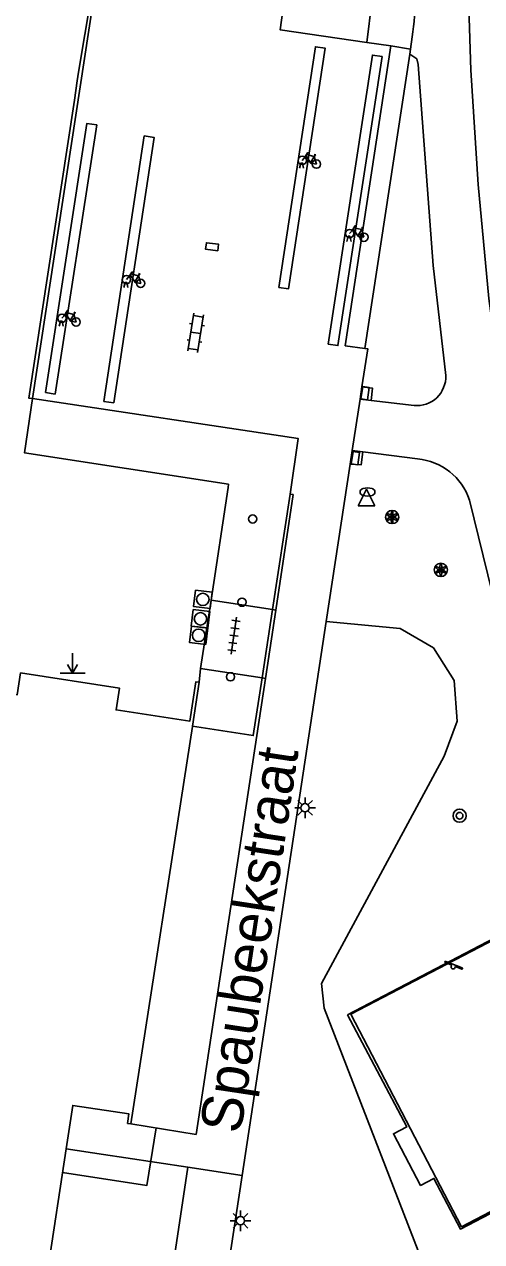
# Model space of a CAD drawing. Extents: x 125000 to 129004, y 397500 to 399008.
# Drawn here: x 126355.6 to 126383.3, y 398833.9 to 398907.4 of the extents above; entities that cross this region are included whole.
import ezdxf

# ---------------------------------------------------------------- set-up
doc = ezdxf.new("R2010")
doc.units = 0
for name, color, linetype in [('bs-afsc-poort', 7, 'Continuous'), ('gg-afsc-hekwerk', 7, 'Continuous'), ('gg-anno-openbare ruimte label', 7, 'Continuous'), ('gg-bbg-hoofdgebouw', 7, 'Continuous'), ('gg-knt-verharding', 7, 'Continuous'), ('gg-knt-verharding nz', 7, 'Continuous'), ('gt-grn-groengrens', 7, 'Continuous'), ('gt-grn-weggrens', 7, 'Continuous'), ('gt-symb-boom', 7, 'Continuous'), ('gt-symb-brandkraan', 7, 'Continuous'), ('gt-symb-fietsenrek', 7, 'Continuous'), ('gt-symb-klinker verharding', 7, 'Continuous'), ('gt-symb-kolk center center', 7, 'Continuous'), ('gt-symb-lichtmast', 7, 'Continuous'), ('gt-symb-markant object', 7, 'Continuous'), ('gt-symb-rioolschacht', 7, 'Continuous'), ('gt-symb-solitaire heester', 7, 'Continuous'), ('gt-symb-speelvoorziening', 7, 'Continuous'), ('gt-symb-tegel verharding', 7, 'Continuous'), ('gt-symb-vlaggenmast', 7, 'Continuous'), ('gt-symb-waterafsluiter', 7, 'Continuous')]:
    doc.layers.add(name, color=color, linetype=linetype)

# ---------------------------------------------------------------- blocks, each defined once
blk = doc.blocks.new('gt0-FREK')
at = {"layer": 'gt-symb-fietsenrek'}
for p, q in [((0.259, 0.762), (0.294, 0.823)), ((0.54, 0.335), (0.259, 0.762)), ((0.294, 0.823), (0.767, 0.714)), ((0.757, 0.841), (0.866, 0.816)), ((0.767, 0.714), (0.84, 0.822)), ((0.767, 0.714), (0.54, 0.335)), ((0.895, 0.252), (0.767, 0.714))]:
    blk.add_line(p, q, dxfattribs=at)
for points in [[(0.036, 0.476), (0.228, 0.708), (0.259, 0.762)], [(0.294, 0.823), (0.36, 0.937), (0.452, 0.935)], [(-0.124, 0), (-0.047, 0.312), (0.053, 0.312), (0.12, 0)], [(0.54, 0.335), (0.555, 0.305), (0.895, 0.252)]]:
    blk.add_lwpolyline(points, dxfattribs=at)
for centre in [(0.036, 0.476), (0.895, 0.252)]:
    blk.add_circle(centre, 0.252, dxfattribs=at)
blk = doc.blocks.new('gt0-KOLKCC')
at = {"layer": 'gt-symb-kolk center center'}
blk.add_lwpolyline([(-0.375, 0.2), (0.375, 0.2), (0.375, -0.2), (-0.375, -0.2)], close=True, dxfattribs=at)
blk = doc.blocks.new('gt0-BR')
at = {"layer": 'gt-symb-brandkraan'}
for centre, radius, start, end in [((-0.244, 0), 0.206, 107.56694, 252.43307), ((0.599, -2.664), 3, 106.89205, 107.56694), ((0, -0.691), 0.938, 73.10799, 106.89205), ((-0.599, -2.664), 3, 72.43309, 73.10799), ((0.244, 0), 0.206, 287.56695, 72.43309), ((0.599, 2.664), 3, 252.43307, 253.10797), ((0, 0.691), 0.938, 253.10797, 286.89206), ((-0.599, 2.664), 3, 286.89206, 287.56695)]:
    blk.add_arc(centre, radius, start, end, dxfattribs=at)
blk = doc.blocks.new('gt0-VMAST')
at = {"layer": 'gt-symb-vlaggenmast'}
blk.add_circle((0, 0), 0.25, dxfattribs=at)
blk = doc.blocks.new('gt0-KL1')
at = {"layer": 'gt-symb-klinker verharding'}
for p, q in [((-1.15, 0.3), (1.15, 0.3)), ((-1, -0.3), (-1, 0.3)), ((-0.5, 0.3), (-0.5, 0.45)), ((0, -0.3), (0, 0.3)), ((0.5, 0.3), (0.5, 0.45)), ((1, -0.3), (1, 0.3)), ((-1.15, -0.3), (1.15, -0.3)), ((-0.5, -0.45), (-0.5, -0.3)), ((0.5, -0.45), (0.5, -0.3))]:
    blk.add_line(p, q, dxfattribs=at)
blk = doc.blocks.new('gt0-MARKOB')
at = {"layer": 'gt-symb-markant object'}
for p, q in [((0, 0), (0, 1.2)), ((-0.75, 0), (0.75, 0)), ((0, 0), (-0.3, 0.52)), ((0, 0), (0.3, 0.52))]:
    blk.add_line(p, q, dxfattribs=at)
blk = doc.blocks.new('gt0-TEG1')
at = {"layer": 'gt-symb-tegel verharding'}
for p, q in [((-1.125, 0), (1.125, 0)), ((-0.9, -0.25), (-0.9, 0.25)), ((-0.45, -0.25), (-0.45, 0.25)), ((0, -0.25), (0, 0.25)), ((0.45, -0.25), (0.45, 0.25)), ((0.9, -0.25), (0.9, 0.25))]:
    blk.add_line(p, q, dxfattribs=at)
blk = doc.blocks.new('gt0-RS')
at = {"layer": 'gt-symb-rioolschacht'}
blk.add_lwpolyline([(-0.5, -0.5), (0.5, -0.5), (0.5, 0.5), (-0.5, 0.5)], close=True, dxfattribs=at)
blk.add_circle((0, 0), 0.375, dxfattribs=at)
blk = doc.blocks.new('gt0-LMAST')
at = {"layer": 'gt-symb-lichtmast'}
for p, q in [((-0.182, 0.173), (-0.447, 0.438)), ((-0.005, 0.246), (-0.005, 0.621)), ((0.172, 0.173), (0.437, 0.438)), ((-0.255, -0.004), (-0.63, -0.004)), ((-0.182, -0.181), (-0.447, -0.446)), ((-0.005, -0.254), (-0.005, -0.629)), ((0.437, -0.446), (0.172, -0.181)), ((0.245, -0.004), (0.62, -0.004))]:
    blk.add_line(p, q, dxfattribs=at)
blk.add_circle((-0.005, -0.004), 0.25, dxfattribs=at)
blk = doc.blocks.new('gt0-SV')
at = {"layer": 'gt-symb-speelvoorziening'}
for p, q in [((-0.477, 0.255), (-0.08, 0.096)), ((0.542, -0.076), (-0.449, 0.324)), ((0.125, 0.014), (0.515, -0.143))]:
    blk.add_line(p, q, dxfattribs=at)
for centre, radius, start, end in [((-0.466, 0.291), 0.0369, 63.6251, 252.66016), ((-0.002, -0.005), 0.128, 127.68665, 8.59861), ((0.531, -0.111), 0.0363, 243.50852, 72.54358)]:
    blk.add_arc(centre, radius, start, end, dxfattribs=at)
blk = doc.blocks.new('gt0-BOOM')
at = {"layer": 'gt-symb-boom'}
for radius in [0.4, 0.2]:
    blk.add_circle((0, 0), radius, dxfattribs=at)
blk = doc.blocks.new('gt0-SH')
at = {"layer": 'gt-symb-solitaire heester'}
blk.add_circle((0, 0), 0.4, dxfattribs=at)
for centre, start, end in [((-0.346, 0.2), 270, 30), ((-0.346, -0.2), 330, 90), ((0, 0.4), 210, 330), ((0.346, 0.2), 150, 270), ((0.346, -0.2), 90, 210), ((0, -0.4), 30, 150)]:
    blk.add_arc(centre, 0.4, start, end, dxfattribs=at)
blk = doc.blocks.new('gt0-WAFSL')
at = {"layer": 'gt-symb-waterafsluiter'}
for p, q in [((-0.5, -0.333), (0, 0.667)), ((0, 0.667), (0.5, -0.333)), ((0.5, -0.333), (-0.5, -0.333))]:
    blk.add_line(p, q, dxfattribs=at)

msp = doc.modelspace()

# ---------------------------------------------------------------- linework, layer by layer
at = {"layer": 'bs-afsc-poort'}
for p, q in [((126359.774, 398909.642), (126358.911, 398904.496)), ((126358.822, 398903.957), (126358.667, 398902.801))]:
    msp.add_line(p, q, dxfattribs=at)
at = {"layer": 'gg-afsc-hekwerk'}
for p, q in [((126359.774, 398909.642), (126358.911, 398904.496)), ((126358.911, 398904.496), (126358.822, 398903.957)), ((126358.822, 398903.957), (126358.667, 398902.801)), ((126371.683, 398879.022), (126370.623, 398872.056)), ((126370.623, 398872.056), (126369.994, 398867.922))]:
    msp.add_line(p, q, dxfattribs=at)
for points in [[(126358.667, 398902.801), (126355.895, 398884.818), (126356.132, 398884.783)], [(126356.132, 398884.783), (126372.169, 398882.386), (126371.683, 398879.022)], [(126365.792, 398865.013), (126369.464, 398864.444), (126369.994, 398867.922)], [(126363.588, 398840.764), (126363.023, 398837.288), (126357.93, 398838.066)]]:
    msp.add_lwpolyline(points, dxfattribs=at)
at = {"layer": 'gg-bbg-hoofdgebouw'}
for p, q in [((126365.792, 398865.013), (126366.203, 398867.667)), ((126362.074, 398841.007), (126365.788, 398864.986)), ((126365.788, 398864.986), (126365.792, 398865.013)), ((126356.757, 398830.38), (126358.149, 398839.499))]:
    msp.add_line(p, q, dxfattribs=at)
for points in [[(126366.203, 398867.667), (126365.995, 398867.699), (126365.628, 398865.307), (126361.17, 398865.992), (126361.373, 398867.316), (126355.403, 398868.233), (126355.2, 398866.909), (126351.256, 398867.514), (126348.904, 398852.204), (126348.179, 398852.322), (126345.955, 398844.083), (126349.086, 398843.608), (126340.733, 398788.77)], [(126358.149, 398839.499), (126358.55, 398842.126), (126361.953, 398841.611), (126361.866, 398841.038), (126362.074, 398841.007)]]:
    msp.add_lwpolyline(points, dxfattribs=at)
at = {"layer": 'gg-knt-verharding'}
for p, q in [((126359.79, 398908.742), (126356.132, 398884.783)), ((126376.318, 398906.285), (126376.633, 398908.727)), ((126379.071, 398906.613), (126378.965, 398905.882)), ((126377.774, 398906.073), (126375.025, 398887.967)), ((126378.965, 398905.882), (126377.774, 398906.073)), ((126378.965, 398905.882), (126378.918, 398905.574)), ((126378.918, 398905.574), (126376.211, 398887.807)), ((126375.025, 398887.967), (126376.211, 398887.807)), ((126376.033, 398885.504), (126375.922, 398884.752)), ((126375.922, 398884.752), (126375.429, 398881.653)), ((126375.922, 398884.752), (126376.582, 398884.674)), ((126376.582, 398884.674), (126379.181, 398884.368)), ((126375.429, 398881.653), (126375.317, 398880.837)), ((126375.429, 398881.653), (126376.076, 398881.57)), ((126376.076, 398881.57), (126379.39, 398881.145)), ((126375.317, 398880.837), (126373.872, 398871.326)), ((126367.94, 398879.414), (126366.919, 398872.618)), ((126367.972, 398879.627), (126367.94, 398879.414)), ((126371.882, 398878.99), (126370.825, 398872.025)), ((126371.683, 398879.022), (126371.882, 398878.99)), ((126366.919, 398872.618), (126366.282, 398868.485)), ((126366.919, 398872.618), (126370.623, 398872.056)), ((126370.825, 398872.025), (126370.197, 398867.891)), ((126370.623, 398872.056), (126370.825, 398872.025)), ((126373.872, 398871.326), (126368.794, 398837.893)), ((126366.282, 398868.485), (126366.203, 398867.667)), ((126366.282, 398868.485), (126369.994, 398867.922)), ((126370.197, 398867.891), (126366.021, 398840.373)), ((126369.994, 398867.922), (126370.197, 398867.891)), ((126366.021, 398840.373), (126362.074, 398841.007)), ((126358.149, 398839.499), (126360.408, 398839.159)), ((126360.408, 398839.159), (126361.766, 398838.954)), ((126361.766, 398838.954), (126365.51, 398838.389)), ((126364.121, 398829.256), (126365.51, 398838.389)), ((126368.794, 398837.893), (126367.404, 398828.742))]:
    msp.add_line(p, q, dxfattribs=at)
for points in [[(126383.746, 398925.691), (126382.824, 398918.632), (126382.379, 398911.59), (126382.618, 398904.611), (126383.048, 398897.702), (126383.699, 398890.836), (126384.221, 398886.944), (126385.581, 398879.252), (126387.076, 398873.07), (126388.945, 398866.626), (126391.425, 398860.451), (126394.519, 398854.069), (126398.17, 398847.756), (126411.83, 398826.688)], [(126371.242, 398908.216), (126371.092, 398907.036), (126376.318, 398906.285)], [(126378.918, 398905.574), (126379.348, 398905.292), (126379.434, 398904.956), (126380.327, 398892.819), (126381.096, 398886.176)], [(126376.211, 398887.807), (126376.389, 398887.783), (126376.033, 398885.504)], [(126376.033, 398885.504), (126376.669, 398885.412), (126376.582, 398884.674)], [(126356.132, 398884.783), (126355.634, 398881.517), (126367.972, 398879.627)], [(126375.317, 398880.837), (126375.975, 398880.779), (126376.076, 398881.57)], [(126382.533, 398878.662), (126384.172, 398871.93), (126385.916, 398865.854), (126388.683, 398858.991), (126391.633, 398852.871), (126395.566, 398846.033), (126409.202, 398825.044), (126413.084, 398818.965), (126416.577, 398812.921), (126419.671, 398806.968), (126422.527, 398800.447), (126425.067, 398793.741), (126426.481, 398789.58)], [(126375.161, 398847.599), (126378.741, 398840.823), (126377.936, 398840.409), (126379.577, 398837.299), (126380.375, 398837.714), (126381.982, 398834.657), (126394.432, 398841.158), (126387.611, 398854.099), (126375.161, 398847.599)], [(126375.365, 398847.622), (126382.055, 398834.802), (126394.162, 398841.125), (126387.466, 398853.934), (126375.365, 398847.622)]]:
    msp.add_lwpolyline(points, dxfattribs=at)
for centre, radius, start, end in [((126345.114, 398910.978), 34.237, 352.67512, 1.10789), ((126379.346, 398886.112), 1.751, 264.60295, 2.10457), ((126379.06, 398877.496), 3.663, 18.55131, 84.83054)]:
    msp.add_arc(centre, radius, start, end, dxfattribs=at)
at = {"layer": 'gg-knt-verharding nz'}
for p, q in [((126377.774, 398906.073), (126376.318, 398906.285)), ((126356.908, 398885.15), (126357.501, 398885.059)), ((126360.442, 398884.605), (126361.037, 398884.528))]:
    msp.add_line(p, q, dxfattribs=at)
for points in [[(126370.998, 398891.499), (126371.591, 398891.409), (126373.813, 398905.927), (126373.22, 398906.018), (126370.998, 398891.499)], [(126373.989, 398888.071), (126374.582, 398887.98), (126377.251, 398905.427), (126376.658, 398905.517), (126373.989, 398888.071)], [(126357.501, 398885.059), (126360.005, 398901.302), (126359.412, 398901.393), (126356.908, 398885.15)], [(126361.037, 398884.528), (126363.473, 398900.547), (126362.88, 398900.637), (126360.442, 398884.605)]]:
    msp.add_lwpolyline(points, dxfattribs=at)
at = {"layer": 'gt-grn-groengrens'}
msp.add_lwpolyline([(126380.11, 398826.774), (126380.534, 398830.489), (126373.756, 398847.993), (126373.578, 398849.479), (126380.991, 398863.205), (126381.78, 398865.324), (126381.602, 398867.78), (126380.348, 398869.746), (126378.333, 398870.905), (126373.872, 398871.326)], dxfattribs=at)
at = {"layer": 'gt-grn-weggrens'}
msp.add_line((126365.51, 398838.389), (126368.794, 398837.893), dxfattribs=at)

# ---------------------------------------------------------------- block references
at = {"layer": 'gt-symb-boom'}
msp.add_blockref('gt0-BOOM', (126381.933, 398859.61), dxfattribs=at)
at = {"layer": 'gt-symb-brandkraan'}
msp.add_blockref('gt0-BR', (126376.367, 398879.148), dxfattribs=at)
at = {"layer": 'gt-symb-fietsenrek'}
for p in [(126372.385, 398898.686), (126375.25, 398894.27), (126361.766, 398891.489), (126357.86, 398889.154)]:
    msp.add_blockref('gt0-FREK', p, dxfattribs=at)
at = {"layer": 'gt-symb-klinker verharding', "rotation": 81.0273733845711}
msp.add_blockref('gt0-KL1', (126365.986, 398888.758), dxfattribs=at)
at = {"layer": 'gt-symb-kolk center center'}
for p, rotation in [((126366.976, 398893.952), 173.1663276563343), ((126376.222, 398885.113), -98.50443006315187), ((126375.636, 398881.187), 81.49556993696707)]:
    msp.add_blockref('gt0-KOLKCC', p, dxfattribs=dict(at, rotation=rotation))
at = {"layer": 'gt-symb-lichtmast'}
for p in [(126372.597, 398860.094), (126368.691, 398835.17)]:
    msp.add_blockref('gt0-LMAST', p, dxfattribs=at)
at = {"layer": 'gt-symb-markant object'}
msp.add_blockref('gt0-MARKOB', (126358.546, 398868.216), dxfattribs=at)
at = {"layer": 'gt-symb-rioolschacht'}
for p, rotation in [((126366.417, 398872.665), -96.94741065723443), ((126366.276, 398871.49), 83.05258934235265), ((126366.163, 398870.498), 83.62817759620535)]:
    msp.add_blockref('gt0-RS', p, dxfattribs=dict(at, rotation=rotation))
at = {"layer": 'gt-symb-solitaire heester'}
for p in [(126377.852, 398877.637), (126380.798, 398874.446)]:
    msp.add_blockref('gt0-SH', p, dxfattribs=at)
at = {"layer": 'gt-symb-speelvoorziening'}
msp.add_blockref('gt0-SV', (126381.542, 398850.496), dxfattribs=at)
at = {"layer": 'gt-symb-tegel verharding', "rotation": 81.9509382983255}
msp.add_blockref('gt0-TEG1', (126368.293, 398870.478), dxfattribs=at)
at = {"layer": 'gt-symb-vlaggenmast'}
for p in [(126369.428, 398877.519), (126368.785, 398872.497), (126368.086, 398867.993)]:
    msp.add_blockref('gt0-VMAST', p, dxfattribs=at)
at = {"layer": 'gt-symb-waterafsluiter'}
msp.add_blockref('gt0-WAFSL', (126376.304, 398878.652), dxfattribs=at)

# ---------------------------------------------------------------- texts
at = {"layer": 'gg-anno-openbare ruimte label'}
msp.add_text('Spaubeekstraat', height=2.5, rotation=81.4, dxfattribs=at).set_placement((126368.697, 398840.363))

doc.saveas('drawing.dxf')
